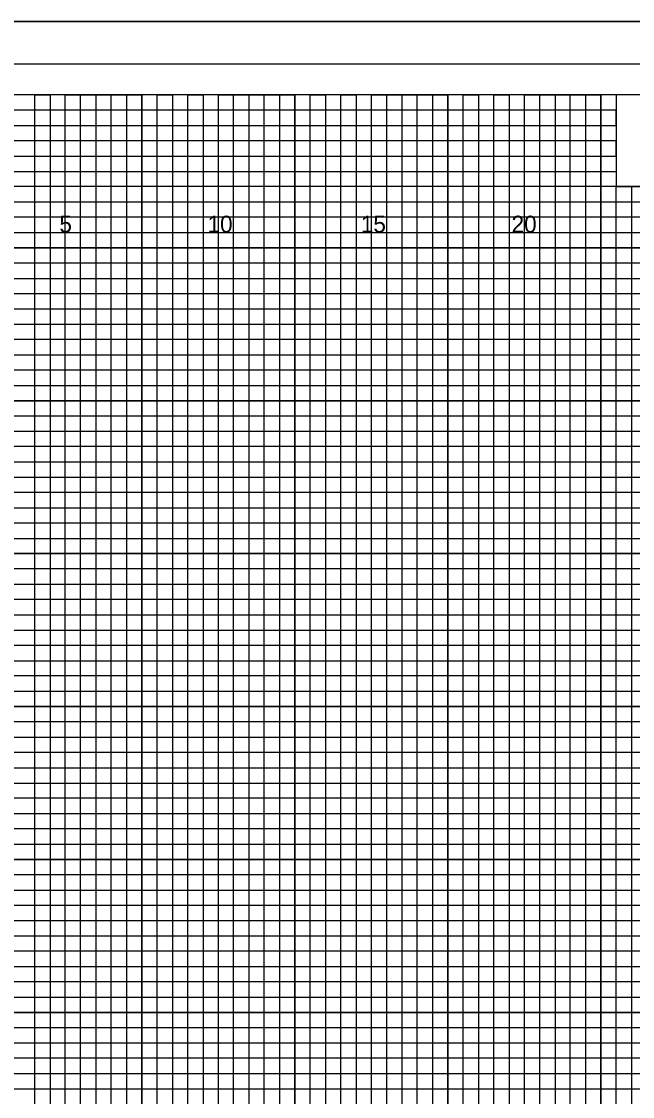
# Model space of a CAD drawing. Extents: x -4 to 103, y -2 to 67.
# Drawn here: x 54.82 to 74.78, y 32.25 to 67.4 of the extents above; entities that cross this region are included whole.
import ezdxf

# ---------------------------------------------------------------- set-up
doc = ezdxf.new("R2010")
doc.units = 0
for name, color, linetype in [('Old_Level_10', 7, 'Continuous'), ('Old_Level_16', 7, 'Continuous'), ('Old_Level_17', 7, 'Continuous'), ('Old_Level_3', 7, 'Continuous'), ('Old_Level_5', 7, 'Continuous'), ('Old_Level_8', 7, 'Continuous'), ('Prop Plan Preparation Sketches Hydraulic Ditch', 7, 'Continuous'), ('Prop XS Dump Level', 7, 'Continuous')]:
    doc.layers.add(name, color=color, linetype=linetype)

msp = doc.modelspace()

# ---------------------------------------------------------------- linework, layer by layer
at = {"layer": 'Old_Level_10'}
for p, q in [((56.25, 0), (56.25, 65)), ((58.75, 0), (58.75, 65)), ((61.25, 0), (61.25, 65)), ((63.75, 0), (63.75, 65)), ((66.25, 0), (66.25, 65)), ((68.75, 0), (68.75, 65)), ((71.25, 0), (71.25, 65)), ((73.75, 0), (73.75, 65)), ((0, 62.5), (74.25, 62.5)), ((0, 60), (102.5, 60)), ((0, 57.5), (102.5, 57.5)), ((0, 55), (102.5, 55)), ((0, 52.5), (102.5, 52.5)), ((0, 50), (102.5, 50)), ((0, 47.5), (102.5, 47.5)), ((0, 45), (102.5, 45)), ((0, 42.5), (102.5, 42.5)), ((0, 40), (102.5, 40)), ((0, 37.5), (102.5, 37.5)), ((0, 35), (102.5, 35)), ((0, 32.5), (102.5, 32.5))]:
    msp.add_line(p, q, dxfattribs=at)
at = {"layer": 'Old_Level_17'}
msp.add_lwpolyline([(103, 66), (-2.8, 66), (-2.8, -1), (103, -1)], close=True, dxfattribs=at)
at = {"layer": 'Old_Level_3'}
msp.add_line((-3.5, 67.4), (103.4, 67.4), dxfattribs=at)
at = {"layer": 'Old_Level_5'}
msp.add_lwpolyline([(103.4, 67.4), (-3.5, 67.4), (-3.5, -2.425), (103.4, -2.425)], close=True, dxfattribs=at)
at = {"layer": 'Old_Level_8'}
for points in [[(56.25, 0), (56.25, 65), (58.75, 65), (58.75, 0)], [(61.25, 0), (61.25, 65), (63.75, 65), (63.75, 0)], [(66.25, 0), (66.25, 65), (68.75, 65), (68.75, 0)], [(71.25, 0), (71.25, 65), (73.75, 65), (73.75, 0)], [(0, 62.5), (74.25, 62.5)], [(0, 57.5), (102.5, 57.5), (102.5, 60), (0, 60)], [(0, 52.5), (102.5, 52.5), (102.5, 55), (0, 55)], [(0, 47.5), (102.5, 47.5), (102.5, 50), (0, 50)], [(0, 42.5), (102.5, 42.5), (102.5, 45), (0, 45)], [(0, 37.5), (102.5, 37.5), (102.5, 40), (0, 40)], [(0, 32.5), (102.5, 32.5), (102.5, 35), (0, 35)]]:
    msp.add_lwpolyline(points, dxfattribs=at)
at = {"layer": 'Prop Plan Preparation Sketches Hydraulic Ditch'}
for points in [[(102.5, 65), (0, 65), (0, 0), (102.5, 0)], [(83.75, 65), (74.25, 65), (74.25, 62), (83.75, 62)]]:
    msp.add_lwpolyline(points, close=True, dxfattribs=at)
at = {"layer": 'Prop XS Dump Level'}
for points in [[(55.25, 0), (55.25, 65), (55.75, 65), (55.75, 0)], [(56.75, 0), (56.75, 65), (57.25, 65), (57.25, 0)], [(57.75, 0), (57.75, 65), (58.25, 65), (58.25, 0)], [(59.25, 0), (59.25, 65), (59.75, 65), (59.75, 0)], [(60.25, 0), (60.25, 65), (60.75, 65), (60.75, 0)], [(61.75, 0), (61.75, 65), (62.25, 65), (62.25, 0)], [(62.75, 0), (62.75, 65), (63.25, 65), (63.25, 0)], [(64.25, 0), (64.25, 65), (64.75, 65), (64.75, 0)], [(65.25, 0), (65.25, 65), (65.75, 65), (65.75, 0)], [(66.75, 0), (66.75, 65), (67.25, 65), (67.25, 0)], [(67.75, 0), (67.75, 65), (68.25, 65), (68.25, 0)], [(69.25, 0), (69.25, 65)], [(69.25, 65), (69.75, 65), (69.75, 0)], [(70.25, 0), (70.25, 65), (70.75, 65), (70.75, 0)], [(71.75, 0), (71.75, 65), (72.25, 65), (72.25, 0)], [(72.75, 0), (72.75, 65), (73.25, 65), (73.25, 0)], [(0, 62), (0, 63), (74.25, 63), (74.25, 63.5), (0, 63.5), (0, 64), (74.25, 64), (74.25, 64.5), (0, 64.5)], [(0, 61.5), (102.5, 61.5), (102.5, 62), (0, 62)], [(74.25, 0), (74.25, 62), (74.75, 62), (74.75, 0)], [(0, 60.5), (102.5, 60.5), (102.5, 61), (0, 61)], [(0, 59), (102.5, 59), (102.5, 59.5), (0, 59.5)], [(0, 58), (102.5, 58), (102.5, 58.5), (0, 58.5)], [(0, 56.5), (102.5, 56.5), (102.5, 57), (0, 57)], [(0, 55.5), (102.5, 55.5), (102.5, 56), (0, 56)], [(0, 54), (102.5, 54), (102.5, 54.5), (0, 54.5)], [(0, 53), (102.5, 53), (102.5, 53.5), (0, 53.5)], [(0, 51.5), (102.5, 51.5), (102.5, 52), (0, 52)], [(0, 50.5), (102.5, 50.5), (102.5, 51), (0, 51)], [(0, 49), (102.5, 49), (102.5, 49.5), (0, 49.5)], [(0, 48), (102.5, 48), (102.5, 48.5), (0, 48.5)], [(0, 46.5), (102.5, 46.5), (102.5, 47), (0, 47)], [(0, 45.5), (102.5, 45.5), (102.5, 46), (0, 46)], [(0, 44), (102.5, 44), (102.5, 44.5), (0, 44.5)], [(0, 43), (102.5, 43), (102.5, 43.5), (0, 43.5)], [(0, 41.5), (102.5, 41.5), (102.5, 42), (0, 42)], [(0, 40.5), (102.5, 40.5), (102.5, 41), (0, 41)], [(0, 39), (102.5, 39), (102.5, 39.5), (0, 39.5)], [(0, 38), (102.5, 38), (102.5, 38.5), (0, 38.5)], [(0, 36.5), (102.5, 36.5), (102.5, 37), (0, 37)], [(0, 35.5), (102.5, 35.5), (102.5, 36), (0, 36)], [(0, 34), (102.5, 34), (102.5, 34.5), (0, 34.5)], [(0, 33), (102.5, 33), (102.5, 33.5), (0, 33.5)]]:
    msp.add_lwpolyline(points, dxfattribs=at)

# ---------------------------------------------------------------- texts
at = {"layer": 'Old_Level_16'}
for s, p in [('5', (56.0574, 60.5)), ('10', (60.8971, 60.5)), ('15', (65.9057, 60.5)), ('20', (70.8312, 60.5))]:
    msp.add_text(s, height=0.55, dxfattribs=at).set_placement(p)

doc.saveas('drawing.dxf')
